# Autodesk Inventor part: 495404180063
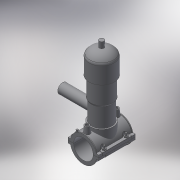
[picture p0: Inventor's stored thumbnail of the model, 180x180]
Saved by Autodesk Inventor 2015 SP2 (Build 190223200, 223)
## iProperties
Created: 2017-07
Part Number: 495404180063
Material: Generic
Description: PLASSON TAPPING VALVE 180-63
Document SubType Name: Modeling
Designer: KIM
Density: 1 g/cm^3
Appearance: Default
Author: KIM
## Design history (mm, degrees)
derived "495404-4954S4.ipt"
feature "Solid1::495404-4954S4.ipt"
feature "Solid2::495404-4954S4.ipt"
tag "TaggingFeature1"
body "Solid1"
body "Solid2"
other parameters: "d3" = 45, "d4" = 118, "d5" = 0, "d6" = 0.1, "d8" = 0, "d19" = 6, "d20" = 6, "d21" = 70.8, "d23" = 0, "d24" = 35.4, "d26" = 0, "d27" = 3, "d28" = 3, "d29" = 3, "d31" = 6, "d32" = 0, "d33" = 0, "d34" = 0.6, "d40" = 109.512, "d47" = 156.3, "d70" = 15, "d72" = 0, "d73" = 6, "d75" = 5, "d76" = 0, "d77" = 9, "d79" = 15, "d80" = 47.2, "d82" = 5 deg, "d84" = 4, "d85" = 14, "d86" = 0, "d87" = 3, "d88" = 0, "d89" = 1, "d90" = 1, "d91" = 94.4, "d92" = 0, "d93" = 0.5, "d94" = 94.73684, "d96" = 216.918, "d97" = 2.36, "d98" = 0, "d120" = 140 deg, "d121" = 24.228, "d122" = 20 deg, "d123" = 421.2, "d124" = 126.36, "d126" = 0, "d143" = 185.4, "d145" = 23.53846, "d149" = 2.7, "d150" = 25.89231, "d153" = 118, "d154" = 0, "d156" = 105.3, "d157" = 160 deg, "d159" = 6.12, "d161" = 2.7, "d162" = 70.8, "d163" = 0, "d167" = 18, "d168" = 102.73171, "d170" = 3, "d172" = 0, "d173" = 1, "d176" = 20 deg, "d177" = 12.6, "d178" = 30.6, "d180" = 0, "d183" = 12.24, "d184" = 10.08, "d185" = 38.35, "d186" = 38.35, "d187" = 105.3, "d188" = 9.18, "d189" = 12.6, "d190" = 0, "d191" = 157.95, "d193" = 6.8, "d194" = 2.95, "d195" = 90 deg, "d197" = 0, "d199" = 0, "d205" = 14.64, "d206" = 81.33333, "d207" = 244, "d208" = 224.48, "d209" = 207.4, "d210" = 200.08, "d211" = 146.4, "d212" = 85.4, "d213" = 65.88, "d214" = 73.2, "d216" = 19.52, "d217" = 70.76, "d218" = 80.52, "d222" = 0, "d223" = 210.6, "d224" = 186, "d225" = 51, "d226" = 63, "d229" = 186, "d230" = 0, "H_" = 186, "L_" = 118, "d_t" = 6, "d_1" = 63, "H_1" = 51, "H_2" = 244, "d148" = 2.7, "d160" = 2.7, "d169" = 3, "d192" = 6.8, "d228" = 50.4
